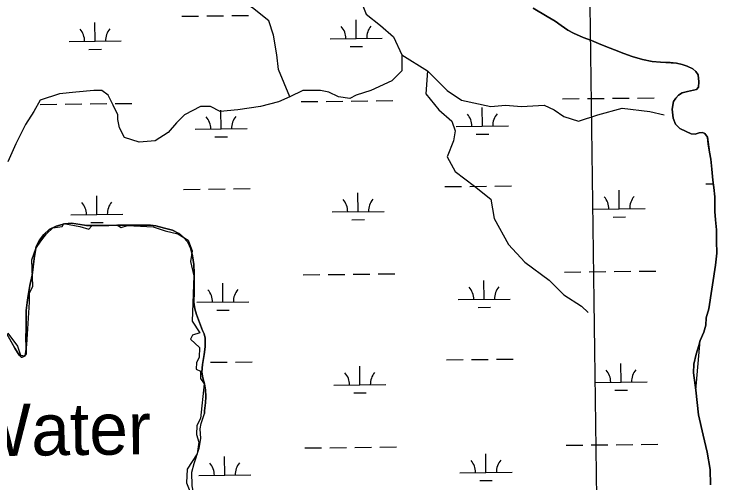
# Model space of a CAD drawing. Extents: x 3734862 to 3772949, y 391520 to 417239.
# Drawn here: x 3766970 to 3768321, y 405120 to 406020 of the extents above; entities that cross this region are included whole.
import ezdxf

# ---------------------------------------------------------------- set-up
doc = ezdxf.new("R2010")
doc.units = 0
for name, color, linetype in [('V-GRID-MAJR', 7, 'Continuous'), ('V-RIVR-IDEN', 7, 'Continuous'), ('V-TOPO-SHOR', 7, 'Continuous'), ('V-WETL-SWMP', 7, 'Continuous')]:
    doc.layers.add(name, color=color, linetype=linetype)

msp = doc.modelspace()

# ---------------------------------------------------------------- linework, layer by layer
at = {"layer": 'V-GRID-MAJR'}
msp.add_spline([(3768195.233, 397232.114), (3768114.148, 403291.314), (3768033.0500000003, 409351.577), (3767951.952, 415411.843), (3767951.938, 415412.9)], degree=3, dxfattribs=at)
at = {"layer": 'V-TOPO-SHOR'}
for p, q in [((3767995.041, 406015.86), (3767968.04, 406031.531)), ((3768009.8340000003, 406006.537), (3767995.041, 406015.86)), ((3768021.663, 405998.337), (3768009.8340000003, 406006.537)), ((3768034.6070000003, 405989.762), (3768021.663, 405998.337)), ((3768045.332, 405983.417), (3768034.6070000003, 405989.762)), ((3768063.836, 405975.565), (3768045.332, 405983.417)), ((3768079.7530000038, 405969.5749999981), (3768063.836, 405975.565)), ((3768093.446, 405963.591), (3768079.7530000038, 405969.5749999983)), ((3768107.511, 405958.348), (3768093.446, 405963.591)), ((3768124.168, 405951.982), (3768107.511, 405958.348)), ((3768142.3050000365, 405944.87199998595), (3768124.168, 405951.982)), ((3768157.849, 405938.881), (3768142.3050000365, 405944.87199998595)), ((3768178.216, 405933.243), (3768157.849, 405938.881)), ((3768196.736, 405929.467), (3768178.216, 405933.2429999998)), ((3768212.6720000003, 405928.295), (3768196.736, 405929.467)), ((3768230.83, 405927.114), (3768212.6720000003, 405928.295)), ((3768243.058, 405926.325), (3768230.83, 405927.114)), ((3768254.169000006, 405923.3189999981), (3768243.058, 405926.325)), ((3768263.7939999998, 405920.316), (3768254.169000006, 405923.3189999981)), ((3768274.896, 405915.086), (3768263.7939999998, 405920.316)), ((3768280.436000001, 405909.8739999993), (3768274.896, 405915.086)), ((3768284.86, 405903.555), (3768280.436000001, 405909.8739999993)), ((3768286.291, 405890.207), (3768284.86, 405903.555)), ((3768285.5130000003, 405880.2), (3768286.291, 405890.207)), ((3768253.9620000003, 405868.82999999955), (3768264.7219999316, 405871.38099998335)), ((3768264.7219999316, 405871.38099998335), (3768281.417, 405875.39699999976)), ((3768281.417, 405875.397), (3768285.5130000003, 405880.2)), ((3768237.5899999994, 405852.581), (3768241.69, 405858.866)), ((3768241.69, 405858.866), (3768247.275, 405864.777)), ((3768247.275, 405864.777), (3768253.9620000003, 405868.8299999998)), ((3768234.94, 405837.76300000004), (3768237.59, 405852.581)), ((3768236.7260000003, 405820.335), (3768234.94, 405837.76300000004)), ((3768241.502, 405808.825), (3768236.7260000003, 405820.335)), ((3768249.9969999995, 405800.637), (3768241.502, 405808.825)), ((3768261.8340000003, 405794.661), (3768249.9969999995, 405800.637)), ((3768271.458, 405790.549), (3768261.8340000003, 405794.661)), ((3768279.2380000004, 405789.40799999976), (3768271.458, 405790.54899999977)), ((3768287.0330000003, 405791.972), (3768279.2380000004, 405789.40799999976)), ((3768292.966, 405792.691), (3768287.0330000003, 405791.972)), ((3768297.779, 405791.18999999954), (3768292.966, 405792.691)), ((3768302.5709999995, 405784.126), (3768297.779, 405791.18999999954)), ((3768304.373, 405770.777), (3768302.5709999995, 405784.126)), ((3768306.5379999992, 405755.20000000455), (3768304.373, 405770.777)), ((3768309.082, 405741.84500000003), (3768306.5379999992, 405755.20000000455)), ((3768311.2320000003, 405722.193), (3768309.082, 405741.84500000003)), ((3768313.376000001, 405701.4239999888), (3768311.2320000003, 405722.193)), ((3768315.1759999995, 405686.961), (3768313.376000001, 405701.4239999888)), ((3768316.9620000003, 405669.53299999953), (3768315.1759999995, 405686.961)), ((3768317.2260000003, 405641.3599999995), (3768316.9620000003, 405669.53299999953)), ((3768318.2770000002, 405625.04600000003), (3768317.2260000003, 405641.3599999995)), ((3767045.13, 405609.80899999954), (3767062.687, 405612.666)), ((3767062.687, 405612.666), (3767065.954, 405617.974)), ((3767065.954, 405617.974), (3767096.573, 405612.666)), ((3767096.573, 405612.666), (3767113.852, 405607.232)), ((3767113.852, 405607.232), (3767119.738, 405613.68200000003)), ((3767119.738, 405613.68200000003), (3767167.901, 405615.793)), ((3767167.901, 405615.793), (3767176.464, 405610.444)), ((3767176.464, 405610.444), (3767188.236, 405614.189)), ((3767188.236, 405614.189), (3767237.468, 405611.51300000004)), ((3768320.4299999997, 405606.13300000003), (3768318.2770000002, 405625.04600000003)), ((3767032.473, 405597.967), (3767045.13, 405609.80899999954)), ((3767237.468, 405611.51300000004), (3767261.0130000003, 405604.021)), ((3767261.0130000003, 405604.021), (3767285.096, 405598.135)), ((3768320.346, 405584.262), (3768320.4299999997, 405606.13300000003)), ((3767021.858, 405584.495), (3767032.473, 405597.967)), ((3767285.096, 405598.135), (3767304.894, 405586.36100000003)), ((3767304.894, 405586.36100000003), (3767312.9220000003, 405565.492)), ((3767012.468, 405569.797), (3767021.858, 405584.495)), ((3768321.001, 405561.277), (3768320.346, 405584.262)), ((3767004.71, 405548.565), (3767012.468, 405569.797)), ((3767312.9220000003, 405565.492), (3767309.176, 405545.157)), ((3768317.9450000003, 405537.936), (3768321.001, 405561.277)), ((3767006.752, 405497.9390000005), (3767004.71, 405548.565)), ((3767309.176, 405545.157), (3767316.133, 405517.866)), ((3768305.395, 405454.21), (3768317.9450000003, 405537.936)), ((3767316.133, 405517.866), (3767312.9220000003, 405430.639)), ((3767000.219, 405484.465), (3767006.752, 405497.9390000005)), ((3767000.219, 405466.91000000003), (3767000.219, 405484.465)), ((3766994.911, 405385.2519999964), (3767000.219, 405466.91000000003)), ((3768300.5109999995, 405436.8059999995), (3768305.395, 405454.21)), ((3768299.347, 405423.0949999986), (3768300.511, 405436.8059999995)), ((3767312.9220000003, 405430.639), (3767327.3710000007, 405408.163)), ((3768295.5870000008, 405409.39400000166), (3768299.347, 405423.0949999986)), ((3766958.165, 405407.708), (3766976.948, 405382.393)), ((3767313.0530000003, 405403.88), (3767309.711, 405395.8539999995)), ((3767327.3710000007, 405408.163), (3767313.0530000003, 405403.88)), ((3768288.915, 405393.09300000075), (3768295.5870000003, 405409.39400000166)), ((3766992.054, 405363.6129999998), (3766994.911, 405385.2519999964)), ((3767309.711, 405395.8539999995), (3767326.8340000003, 405379.8019999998)), ((3768280.7090000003, 405297.876), (3768288.915, 405393.09300000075)), ((3766976.948, 405382.393), (3766983.071, 405365.245)), ((3767326.8340000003, 405379.802), (3767326.3000000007, 405360.5360000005)), ((3766983.071, 405365.245), (3766992.054, 405363.6129999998)), ((3767326.3000000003, 405360.5360000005), (3767320.948, 405350.9049999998)), ((3767320.948, 405350.9049999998), (3767320.414, 405338.06200000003)), ((3767320.414, 405338.06200000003), (3767328.4399999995, 405334.316)), ((3767328.4399999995, 405334.316), (3767328.4399999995, 405320.40199999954)), ((3767328.4399999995, 405320.40199999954), (3767335.397, 405310.23299999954)), ((3767335.397, 405310.23299999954), (3767328.44, 405243.344)), ((3768285.861, 405250.729), (3768280.7090000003, 405297.876)), ((3768294.481000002, 405211.752999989), (3768285.861, 405250.729)), ((3767328.4399999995, 405243.344), (3767321.485, 405229.9640000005)), ((3767321.485, 405229.9640000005), (3767320.657, 405212.88)), ((3767320.657, 405212.88), (3767325.231, 405198.392)), ((3768302.458, 405178.92799999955), (3768294.481000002, 405211.752999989)), ((3767325.231, 405198.392), (3767322.019, 405175.381)), ((3767322.019, 405175.381), (3767302.754, 405145.949)), ((3768307.699, 405145.43700000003), (3768302.458, 405178.92799999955)), ((3767302.754, 405145.949), (3767301.685, 405120.26300000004)), ((3768308.8729999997, 405116.071), (3768307.699, 405145.43700000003)), ((3767301.685, 405120.26300000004), (3767314.608, 405087.968))]:
    msp.add_line(p, q, dxfattribs=at)
for points in [[(3767500.281752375, 405861.24585324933), (3767478.477634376, 405914.198711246), (3767475.362760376, 405942.2325772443), (3767469.1330123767, 405979.6110652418), (3767459.788390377, 406007.64493124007), (3767428.6396503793, 406032.56392323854), (3767385.031414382, 406060.5977892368), (3767366.342170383, 406079.28703323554), (3767356.9975483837, 406094.8614032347), (3767344.5380523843, 406119.7803952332), (3767316.5041863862, 406157.1588832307), (3767297.814942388, 406169.61837923), (3767279.1256983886, 406175.8481272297)], [(3767624.953, 406075.092), (3767646.680830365, 406020.10442723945), (3767674.7146963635, 405998.3003092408), (3767699.6336883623, 405976.49619124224), (3767715.208058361, 405942.2325772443), (3767715.208058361, 405911.0838372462), (3767696.5188143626, 405892.39459324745), (3767656.025452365, 405873.70534924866), (3767627.9915863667, 405864.3607272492), (3767615.5320903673, 405858.1309792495), (3767593.7279723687, 405861.24585324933), (3767575.03872837, 405870.5904752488), (3767559.4643583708, 405873.70534924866), (3767525.2007443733, 405873.70534924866), (3767500.281752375, 405861.24585324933), (3767478.477634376, 405851.90123125), (3767444.2140203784, 405842.55660925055), (3767400.605784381, 405836.3268612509), (3767366.342170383, 405833.21198725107), (3767347.652926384, 405842.55660925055), (3767328.9636823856, 405842.55660925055), (3767297.814942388, 405826.9822392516), (3767282.2405723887, 405811.40786925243), (3767266.666202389, 405792.7186252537), (3767241.7472103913, 405777.14425525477), (3767210.598470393, 405774.0293812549), (3767182.564604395, 405783.37400325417), (3767173.2199823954, 405802.0632472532), (3767170.1051083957, 405817.6376172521), (3767170.1051083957, 405826.9822392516), (3767160.760486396, 405845.6714832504), (3767151.415864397, 405864.3607272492), (3767138.956368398, 405873.70534924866), (3767123.3819983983, 405873.70534924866), (3767089.1183844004, 405870.5904752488), (3767057.9696444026, 405867.47560124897), (3767020.5911564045, 405855.01610524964), (3767008.1316604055, 405833.21198725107), (3766992.5572904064, 405808.29299525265), (3766973.8680464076, 405770.9145072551), (3766958.293676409, 405736.6508932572)], [(3767968.04, 406031.531), (3767995.041, 406015.86), (3768009.8340000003, 406006.537), (3768021.663, 405998.337), (3768034.6070000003, 405989.762), (3768045.332, 405983.419), (3768063.836, 405975.565), (3768079.753, 405969.575), (3768093.446, 405963.591)], [(3768093.446, 405963.591), (3768107.511, 405958.348), (3768124.168, 405951.982), (3768142.305, 405944.87200000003), (3768157.849, 405938.881), (3768178.216, 405933.243), (3768196.736, 405929.467), (3768212.6720000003, 405928.295), (3768230.83, 405927.114), (3768243.058, 405926.325), (3768254.169, 405923.319), (3768263.794, 405920.316), (3768274.896, 405915.086), (3768280.436, 405909.874), (3768284.86, 405903.555), (3768286.291, 405890.207), (3768285.5130000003, 405880.2), (3768281.417, 405875.397), (3768264.722, 405871.38300000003), (3768253.9620000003, 405868.83), (3768247.275, 405864.777), (3768241.69, 405858.866), (3768237.59, 405852.581), (3768234.94, 405837.76300000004), (3768236.7260000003, 405820.335), (3768241.502, 405808.825), (3768249.997, 405800.637), (3768261.8340000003, 405794.661), (3768271.458, 405790.549), (3768279.238, 405789.406), (3768287.0330000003, 405791.972), (3768292.966, 405792.691), (3768297.779, 405791.19), (3768302.571, 405784.128), (3768304.373, 405770.777), (3768306.538, 405755.2), (3768309.082, 405741.84500000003), (3768311.2320000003, 405722.193), (3768313.376, 405701.424), (3768315.176, 405686.961), (3768316.9620000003, 405669.533), (3768317.2260000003, 405641.36), (3768318.2770000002, 405625.04600000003), (3768320.43, 405606.13300000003), (3768320.346, 405584.262), (3768321.001, 405561.277), (3768317.9450000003, 405537.936), (3768305.395, 405454.21), (3768300.511, 405436.806), (3768299.347, 405423.09500000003), (3768295.5870000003, 405409.39400000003), (3768288.915, 405393.093)], [(3767715.208058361, 405942.2325772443), (3767765.046042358, 405911.0838372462), (3767802.4245303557, 405873.70534924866), (3767830.4583963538, 405855.01610524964), (3767886.5261283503, 405842.55660925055), (3767914.559994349, 405845.6714832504), (3767945.7087343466, 405842.55660925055), (3767989.3169703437, 405845.6714832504), (3768008.0062143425, 405836.3268612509), (3768026.695458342, 405823.86736525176), (3768054.72932434, 405814.5227432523), (3768092.1078123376, 405826.9822392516), (3768138.830922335, 405839.4417352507), (3768191.7837803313, 405833.21198725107), (3768219.8176463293, 405826.9822392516)], [(3767765.046042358, 405911.0838372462), (3767761.931168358, 405867.47560124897), (3767786.8501603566, 405836.3268612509), (3767811.7691523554, 405814.5227432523), (3767817.9989003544, 405795.8334992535), (3767814.8840263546, 405777.14425525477), (3767802.4245303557, 405745.99551525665), (3767817.9989003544, 405717.9616492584), (3767855.3773883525, 405689.9277832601), (3767886.5261283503, 405665.0087912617), (3767892.75587635, 405627.63030326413), (3767920.7897423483, 405577.7923192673), (3767951.9384823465, 405543.52870526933), (3767998.6615923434, 405509.26509127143), (3768026.695458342, 405481.2312252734), (3768060.9590723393, 405459.42710727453), (3768073.4185683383, 405446.96761127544)], [(3766993.502, 405367.778), (3766993.549, 405380.199), (3766993.2290000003, 405398.832), (3766993.68, 405415.132), (3766993.8170000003, 405451.232), (3766995.816, 405466.363), (3766997.419, 405479.941), (3767000.987, 405499.336), (3767004.9420000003, 405518.728), (3767007.332, 405534.635), (3767009.74, 405555.586), (3767012.915, 405573.817), (3767019.558, 405585.825), (3767027.363, 405596.66500000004), (3767037.882, 405606.716), (3767051.491, 405612.875), (3767067.4220000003, 405617.472), (3767081.0130000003, 405618.58400000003), (3767094.202, 405616.594), (3767109.72, 405614.208), (3767132.233, 405614.509), (3767152.416, 405614.433), (3767169.4990000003, 405615.14400000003), (3767190.069, 405614.679), (3767209.478, 405614.992), (3767232.378, 405614.906), (3767242.8540000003, 405613.313), (3767259.529, 405609.368), (3767275.038, 405605.041), (3767287.0500000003, 405598.784), (3767295.174, 405592.155), (3767304.452, 405582.028), (3767310.227, 405569.197), (3767313.2800000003, 405555.987), (3767315.935, 405539.286), (3767316.258, 405522.59500000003), (3767316.201, 405507.069), (3767316.5100000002, 405486.495), (3767316.0470000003, 405466.701), (3767317.5530000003, 405454.273), (3767321.003, 405443.003), (3767332.532, 405412.29600000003), (3767336.001, 405406.072), (3767337.912, 405397.912), (3767337.4590000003, 405381.223), (3767335.8510000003, 405366.48), (3767333.48, 405355.232), (3767332.286, 405347.472), (3767331.065, 405332.729), (3767332.964, 405321.465), (3767336.026, 405310.197), (3767338.311, 405298.543), (3767338.647, 405284.955), (3767338.217, 405273.701), (3767336.605, 405258.569), (3767336.5870000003, 405253.135)], [(3766964.4790000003, 405391.955), (3766972.1920000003, 405378.34), (3766980.292, 405365.112), (3766984.161, 405361.216), (3766986.1, 405361.208), (3766990.7660000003, 405363.131), (3766993.502, 405367.778)], [(3768280.7090000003, 405297.876), (3768276.1780000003, 405331.101), (3768276.625, 405348.08900000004), (3768281.1180000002, 405367.172), (3768286.328, 405383.548), (3768288.915, 405393.093)], [(3768280.7090000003, 405297.876), (3768285.861, 405250.729), (3768294.481, 405211.753), (3768302.458, 405178.928), (3768307.699, 405145.43700000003), (3768308.873, 405116.071)], [(3767214.315, 404796.22000000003), (3767228.0840000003, 404813.19800000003), (3767247.316, 404830.825), (3767264.481, 404845.05100000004), (3767280.969, 404860.646), (3767293.38, 404878.998), (3767308.019, 404924.648), (3767312.992, 404953.976), (3767318.02, 404991.495), (3767320.287, 405024.93700000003), (3767321.882, 405059.749), (3767317.309, 405091.188), (3767312.682, 405114.43200000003), (3767312.17, 405140.381), (3767316.379, 405157.424), (3767326.132, 405186.719), (3767328.983, 405205.134), (3767327.739, 405223.578), (3767329.855, 405233.806), (3767336.5870000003, 405253.135)]]:
    msp.add_lwpolyline(points, dxfattribs=at)
at = {"layer": 'V-WETL-SWMP'}
for p, q in [((3767388.623544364, 406017.3598619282), (3767420.621759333, 406017.69785416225)), ((3767126.064624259, 405968.1539022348), (3767125.6843829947, 406004.15189407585)), ((3767292.628899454, 406016.3458852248), (3767324.6271144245, 406016.6838774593)), ((3767340.6262219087, 406016.85287357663), (3767372.624436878, 406017.1908658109)), ((3767627.944626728, 405973.45518368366), (3767627.564385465, 406009.4531755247)), ((3767076.0674133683, 405967.6257893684), (3767176.061835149, 405968.6820151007)), ((3767577.9474158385, 405972.9270708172), (3767677.9418376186, 405973.9832965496)), ((3767114.228279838, 405952.59701592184), (3767138.226941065, 405952.850510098)), ((3767616.1082823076, 405957.8982973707), (3767640.106943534, 405958.15179154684)), ((3768024.25480999, 405857.5636491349), (3768056.2530249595, 405857.90164136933)), ((3768072.2521324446, 405858.07063748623), (3768104.2503474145, 405858.4086297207)), ((3768120.249454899, 405858.57762583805), (3768152.247669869, 405858.91561807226)), ((3768168.2467773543, 405859.08461418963), (3768200.244992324, 405859.42260642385)), ((3767020.494805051, 405846.9610862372), (3767052.4930200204, 405847.29907847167)), ((3767068.4921275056, 405847.46807458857), (3767100.490342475, 405847.806066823)), ((3767116.4894499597, 405847.9750629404), (3767148.4876649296, 405848.3130551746)), ((3767164.4867724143, 405848.48205129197), (3767196.4849873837, 405848.8200435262)), ((3767522.3748075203, 405852.262367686), (3767554.37302249, 405852.6003599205)), ((3767570.372129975, 405852.7693560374), (3767602.370344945, 405853.1073482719)), ((3767618.36945243, 405853.2763443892), (3767650.3676673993, 405853.61433662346)), ((3767666.3667748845, 405853.7833327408), (3767698.364989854, 405854.12132497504)), ((3767368.327381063, 405799.89035770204), (3767367.947139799, 405835.8883495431)), ((3767870.2073835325, 405805.19163915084), (3767869.827142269, 405841.18963099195)), ((3767820.2101726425, 405804.6635262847), (3767920.204594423, 405805.719752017)), ((3767318.3301701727, 405799.3622448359), (3767418.3245919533, 405800.4184705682)), ((3767858.371039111, 405789.6347528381), (3767882.369700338, 405789.8882470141)), ((3767356.491036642, 405784.3334713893), (3767380.489697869, 405784.5869655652)), ((3768299.902703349, 405694.29200546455), (3768314.2454027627, 405694.44350519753)), ((3767296.142698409, 405683.6894425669), (3767328.14091338, 405684.02743480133)), ((3767344.140020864, 405684.1964309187), (3767376.1382358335, 405684.5344231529)), ((3767392.137343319, 405684.7034192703), (3767424.1355582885, 405685.04141150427)), ((3767798.0227008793, 405688.99072401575), (3767830.020915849, 405689.3287162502)), ((3767846.020023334, 405689.49771236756), (3767878.0182383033, 405689.8357046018)), ((3767894.0173457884, 405690.00470071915), (3767926.0155607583, 405690.3426929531)), ((3768133.338428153, 405646.10002247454), (3768132.9581868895, 405682.0980143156)), ((3767129.578423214, 405635.4974595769), (3767129.19818195, 405671.4954514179)), ((3767631.4584256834, 405640.7987410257), (3767631.07818442, 405676.7967328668)), ((3767581.4612147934, 405640.2706281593), (3767681.455636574, 405641.3268538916)), ((3768083.341217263, 405645.57190960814), (3768183.3356390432, 405646.62813534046)), ((3767079.5812123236, 405634.9693467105), (3767179.5756341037, 405636.0255724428)), ((3768121.5020837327, 405630.5431361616), (3768145.5007449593, 405630.7966303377)), ((3767117.742078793, 405619.9405732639), (3767141.74074002, 405620.19406744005)), ((3767619.6220812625, 405625.2418547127), (3767643.62074249, 405625.49534888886)), ((3767525.888606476, 405519.6059250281), (3767557.8868214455, 405519.94391726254)), ((3767573.8859289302, 405520.11291337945), (3767605.8841439, 405520.4509056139)), ((3767621.883251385, 405520.61990173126), (3767653.8814663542, 405520.9578939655)), ((3767669.8805738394, 405521.12689008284), (3767701.878788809, 405521.46488231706)), ((3768027.7686089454, 405524.90720647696), (3768059.7668239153, 405525.2451987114)), ((3768075.7659314, 405525.4141948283), (3768107.76414637, 405525.75218706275)), ((3768123.763253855, 405525.9211831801), (3768155.7614688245, 405526.25917541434)), ((3768171.760576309, 405526.4281715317), (3768203.758791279, 405526.7661637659)), ((3767873.7211824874, 405472.5351964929), (3767873.3409412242, 405508.53318833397)), ((3767371.8411800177, 405467.23391504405), (3767371.460938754, 405503.23190688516)), ((3767321.8439691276, 405466.7058021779), (3767421.838390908, 405467.7620279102)), ((3767823.723971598, 405472.00708362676), (3767923.7183933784, 405473.0633093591)), ((3767360.0048355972, 405451.6770287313), (3767384.0034968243, 405451.9305229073)), ((3767861.8848380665, 405456.9783101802), (3767885.883499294, 405457.2318043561)), ((3767801.536499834, 405356.33428135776), (3767833.5347148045, 405356.67227359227)), ((3767849.533822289, 405356.8412697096), (3767881.5320372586, 405357.17926194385)), ((3767897.531144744, 405357.34825806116), (3767929.5293597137, 405357.6862502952)), ((3767347.6538198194, 405351.5399882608), (3767379.6520347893, 405351.877980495)), ((3767395.651142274, 405352.04697661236), (3767427.6493572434, 405352.38496884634)), ((3767634.972224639, 405308.14229836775), (3767634.591983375, 405344.1402902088)), ((3768136.8522271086, 405313.4435798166), (3768136.471985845, 405349.44157165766)), ((3767584.9750137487, 405307.61418550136), (3767684.969435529, 405308.6704112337)), ((3768086.855016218, 405312.91546695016), (3768186.849437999, 405313.97169268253)), ((3767623.1358802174, 405292.5854120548), (3767647.134541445, 405292.8389062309)), ((3768125.0158826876, 405297.88669350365), (3768149.0145439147, 405298.1401876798)), ((3768175.274375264, 405193.7717288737), (3768207.272590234, 405194.109721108)), ((3767529.402405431, 405186.94948237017), (3767561.4006204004, 405187.2874746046)), ((3767577.399727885, 405187.4564707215), (3767609.397942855, 405187.79446295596)), ((3767625.3970503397, 405187.96345907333), (3767657.3952653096, 405188.30145130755)), ((3767673.394372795, 405188.4704474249), (3767705.392587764, 405188.80843965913)), ((3768031.282407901, 405192.25076381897), (3768063.2806228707, 405192.5887560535)), ((3768079.2797303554, 405192.7577521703), (3768111.277945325, 405193.0957444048)), ((3768127.27705281, 405193.26474052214), (3768159.2752677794, 405193.6027327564)), ((3767375.354978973, 405134.5774723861), (3767374.974737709, 405170.57546422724)), ((3767877.2349814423, 405139.878753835), (3767876.854740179, 405175.87674567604)), ((3767827.2377705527, 405139.3506409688), (3767927.2321923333, 405140.40686670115)), ((3767325.3577680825, 405134.04935951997), (3767425.352189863, 405135.1055852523)), ((3767865.398637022, 405124.32186752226), (3767889.3972982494, 405124.57536169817))]:
    msp.add_line(p, q, dxfattribs=at)
for points in [[(3767968.041, 406031.531), (3767995.042, 406015.86), (3768009.8340000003, 406006.537), (3768021.664, 405998.337), (3768034.606, 405989.762), (3768045.3310000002, 405983.42), (3768063.836, 405975.565), (3768079.752, 405969.574), (3768093.4450000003, 405963.591), (3768107.511, 405958.348), (3768124.168, 405951.983), (3768157.85, 405938.882), (3768178.216, 405933.244), (3768196.736, 405929.467), (3768212.671, 405928.295), (3768243.059, 405926.326), (3768254.169, 405923.318), (3768263.795, 405920.316), (3768274.896, 405915.085), (3768280.436, 405909.874), (3768284.86, 405903.556), (3768286.292, 405890.206), (3768285.5130000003, 405880.2), (3768281.417, 405875.397), (3768253.9620000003, 405868.829), (3768247.274, 405864.777), (3768241.691, 405858.867), (3768237.59, 405852.581), (3768234.9390000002, 405837.76300000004), (3768236.7260000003, 405820.335), (3768241.502, 405808.825), (3768249.9960000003, 405800.63800000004), (3768261.835, 405794.662), (3768271.458, 405790.548), (3768279.238, 405789.407), (3768287.032, 405791.972), (3768292.965, 405792.691), (3768297.778, 405791.19), (3768302.571, 405784.128), (3768306.538, 405755.2), (3768309.082, 405741.846), (3768313.377, 405701.425), (3768315.176, 405686.962), (3768316.963, 405669.533), (3768317.227, 405641.36), (3768318.2770000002, 405625.04600000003), (3768320.429, 405606.13300000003), (3768320.346, 405584.26300000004), (3768321, 405561.278), (3768317.946, 405537.93700000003), (3768305.396, 405454.21), (3768300.511, 405436.806), (3768299.347, 405423.09500000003), (3768295.588, 405409.39400000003), (3768288.915, 405393.094), (3768286.328, 405383.548), (3768281.1180000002, 405367.172), (3768276.6240000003, 405348.08900000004), (3768276.1780000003, 405331.10000000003), (3768280.7090000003, 405297.875), (3768285.861, 405250.729), (3768294.481, 405211.754), (3768302.458, 405178.928), (3768307.7, 405145.43700000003), (3768308.872, 405116.07)], [(3767338.216, 405273.701), (3767338.647, 405284.956), (3767338.311, 405298.543), (3767336.026, 405310.196), (3767332.963, 405321.46400000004), (3767331.065, 405332.728), (3767332.286, 405347.473), (3767333.48, 405355.232), (3767335.8510000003, 405366.48), (3767337.46, 405381.224), (3767337.911, 405397.913), (3767336.002, 405406.071), (3767332.532, 405412.295), (3767321.004, 405443.003), (3767317.5530000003, 405454.273), (3767316.0470000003, 405466.7), (3767316.511, 405486.494), (3767316.201, 405507.068), (3767316.259, 405522.594), (3767315.935, 405539.286), (3767313.281, 405555.987), (3767310.2260000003, 405569.196), (3767304.452, 405582.027), (3767295.1750000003, 405592.154), (3767287.049, 405598.784), (3767275.039, 405605.04000000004), (3767259.529, 405609.368), (3767242.8540000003, 405613.313), (3767232.379, 405614.906), (3767209.478, 405614.992), (3767190.069, 405614.678), (3767169.4990000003, 405615.14400000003), (3767152.417, 405614.433), (3767132.233, 405614.509), (3767109.719, 405614.207), (3767081.012, 405618.585), (3767067.4220000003, 405617.472), (3767051.49, 405612.875), (3767037.881, 405606.716), (3767027.363, 405596.664), (3767019.558, 405585.825), (3767012.914, 405573.817), (3767009.74, 405555.586), (3767007.3310000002, 405534.634), (3767004.9420000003, 405518.729), (3767000.987, 405499.336), (3766997.42, 405479.942), (3766995.815, 405466.362), (3766993.8170000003, 405451.232), (3766993.68, 405415.13300000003), (3766993.23, 405398.832), (3766993.548, 405380.2), (3766993.501, 405367.779), (3766990.7660000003, 405363.131), (3766986.1010000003, 405361.208), (3766984.16, 405361.216), (3766980.293, 405365.112), (3766972.1920000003, 405378.34), (3766949.828, 405417.629)], [(3767312.683, 405114.43200000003), (3767312.17, 405140.381), (3767316.379, 405157.423), (3767326.131, 405186.718), (3767328.983, 405205.135), (3767327.739, 405223.578), (3767329.855, 405233.806), (3767336.586, 405253.135), (3767336.606, 405258.569), (3767338.216, 405273.701)]]:
    msp.add_lwpolyline(points, dxfattribs=at)
for centre, radius, start, end in [((3767070.8197547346, 405968.04518882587), 35.24628790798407, 359.8333639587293, 41.377022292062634), ((3767181.2994637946, 405969.21216903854), 35.24628790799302, 139.83336095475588, 181.3770192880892), ((3767572.699757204, 405973.3464702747), 35.24628790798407, 359.8333639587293, 41.377022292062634), ((3767683.179466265, 405974.5134504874), 35.24628790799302, 139.83336095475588, 181.3770192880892), ((3767925.4422230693, 405806.2499059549), 35.24628790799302, 139.83336095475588, 181.3770192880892), ((3767313.082511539, 405799.7816442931), 35.24628790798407, 359.8333639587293, 41.377022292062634), ((3767423.562220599, 405800.948624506), 35.24628790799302, 139.83336095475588, 181.3770192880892), ((3767814.9625140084, 405805.0829257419), 35.24628790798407, 359.8333639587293, 41.377022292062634), ((3768078.093558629, 405645.9913090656), 35.24628790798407, 359.8333639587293, 41.377022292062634), ((3768188.57326769, 405647.1582892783), 35.24628790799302, 139.83336095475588, 181.3770192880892), ((3767074.33355369, 405635.3887461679), 35.24628790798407, 359.8333639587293, 41.377022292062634), ((3767184.8132627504, 405636.5557263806), 35.24628790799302, 139.83336095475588, 181.3770192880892), ((3767576.2135561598, 405640.69002761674), 35.24628790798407, 359.8333639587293, 41.377022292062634), ((3767686.6932652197, 405641.8570078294), 35.24628790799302, 139.83336095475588, 181.3770192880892), ((3767427.0760195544, 405468.2921818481), 35.24628790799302, 139.83336095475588, 181.3770192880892), ((3767818.476312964, 405472.426483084), 35.24628790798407, 359.8333639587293, 41.377022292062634), ((3767928.956022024, 405473.5934632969), 35.24628790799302, 139.83336095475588, 181.3770192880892), ((3767316.5963104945, 405467.1252016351), 35.24628790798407, 359.8333639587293, 41.377022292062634), ((3767579.727355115, 405308.0335849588), 35.24628790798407, 359.8333639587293, 41.377022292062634), ((3767690.207064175, 405309.2005651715), 35.24628790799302, 139.83336095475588, 181.3770192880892), ((3768081.6073575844, 405313.3348664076), 35.24628790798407, 359.8333639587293, 41.377022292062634), ((3768192.087066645, 405314.50184662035), 35.24628790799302, 139.83336095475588, 181.3770192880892), ((3767320.1101094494, 405134.4687589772), 35.24628790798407, 359.8333639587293, 41.377022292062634), ((3767430.5898185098, 405135.6357391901), 35.24628790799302, 139.83336095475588, 181.3770192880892), ((3767821.9901119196, 405139.770040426), 35.24628790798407, 359.8333639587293, 41.377022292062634), ((3767932.469820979, 405140.93702063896), 35.24628790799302, 139.83336095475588, 181.3770192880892)]:
    msp.add_arc(centre, radius, start, end, dxfattribs=at)

# ---------------------------------------------------------------- texts
at = {"layer": 'V-RIVR-IDEN'}
msp.add_text('Water', height=99.99980199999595, rotation=0.7119027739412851, dxfattribs=at).set_placement((3766877.6831417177, 405170.6564184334))

doc.saveas('drawing.dxf')
